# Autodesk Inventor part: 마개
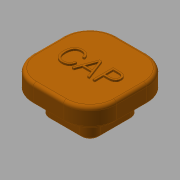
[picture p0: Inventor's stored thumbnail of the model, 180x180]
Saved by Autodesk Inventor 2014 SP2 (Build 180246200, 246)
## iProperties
Created: 2018-03
Part Number: 마개
Material: 고무
Document SubType Name: Modeling
Designer: mduedu
Density: 1 g/cm^3
Appearance: 주황색
Author: mduedu
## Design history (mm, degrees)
sketch "스케치1"
  geometry: L1 (12.5, 12.5)-(-12.5, 12.5); L2 (-12.5, 12.5)-(-12.5, -12.5); L3 (-12.5, -12.5)-(12.5, -12.5); L4 (12.5, -12.5)-(12.5, 12.5); L5 (12.5, 12.5)-(-12.5, -12.5); L6 (-12.5, 12.5)-(12.5, -12.5); 1 further point
  constraints: 12 end point, 2 midpoint, 2 parallel, 1 horizontal, 1 perpendicular
  dimensions: "d0" = 25 distance of L3.end L2.end; "d1" = 25 distance of L2.end L1.end
extrude "돌출1" new body sketch "스케치1" distance "d2" = 6; taper "d3" = 0 deg
fillet "모깎기1" dims "d4" = 8
fillet "모깎기2" dims "d5" = 1
sketch "스케치2"
  geometry: L1 (4.5, -12.5)-(-4.5, -12.5) reference; L2 (12.5, 4.5)-(12.5, -4.5) reference; L3 (-4.5, 12.5)-(4.5, 12.5) reference; L4 (-12.5, -4.5)-(-12.5, 4.5) reference; L5 (7.5, 4.5)-(7.5, -4.5); L6 (4.5, -7.5)-(-4.5, -7.5); L7 (-7.5, -4.5)-(-7.5, 4.5); L8 (-4.5, 7.5)-(4.5, 7.5); A1 r 8 centre (-4.5, -4.5) between (-12.5, -4.5) and (-4.5, -12.5) reference; A2 r 8 centre (4.5, -4.5) between (4.5, -12.5) and (12.5, -4.5) reference; A3 r 8 centre (4.5, 4.5) between (12.5, 4.5) and (4.5, 12.5) reference; A4 r 8 centre (-4.5, 4.5) between (-4.5, 12.5) and (-12.5, 4.5) reference; A5 r 3 centre (4.5, 4.5) between (7.5, 4.5) and (4.5, 7.5); A6 r 3 centre (4.5, -4.5) between (4.5, -7.5) and (7.5, -4.5); A7 r 3 centre (-4.5, -4.5) between (-7.5, -4.5) and (-4.5, -7.5); A8 r 3 centre (-4.5, 4.5) between (-4.5, 7.5) and (-7.5, 4.5); 1 further point
  constraints: 8 end point, 8 point on circle, 4 centre point, 7 other
  dimensions: "d6" = 5 distance between parallel lines of L8 L3
extrude "돌출2" join sketch "스케치2" distance "d7" = 6; taper "d8" = 0 deg
sketch "스케치3"
  geometry: L1 (4.5, 7.5)-(-4.5, 7.5) reference; L2 (-7.5, 4.5)-(-7.5, -4.5) reference; L3 (-4.5, -7.5)-(4.5, -7.5) reference; L4 (7.5, -4.5)-(7.5, 4.5) reference; L5 (-4.5, 5)-(4.5, 5); L6 (5, 4.5)-(5, -4.5); L7 (4.5, -5)-(-4.5, -5); L8 (-5, -4.5)-(-5, 4.5); A1 r 3 centre (4.5, 4.5) between (7.5, 4.5) and (4.5, 7.5) reference; A2 r 3 centre (-4.5, 4.5) between (-4.5, 7.5) and (-7.5, 4.5) reference; A3 r 3 centre (-4.5, -4.5) between (-7.5, -4.5) and (-4.5, -7.5) reference; A4 r 3 centre (4.5, -4.5) between (4.5, -7.5) and (7.5, -4.5) reference; A5 r 0.5 centre (4.5, 4.5) between (5, 4.5) and (4.5, 5); A6 r 0.5 centre (4.5, -4.5) between (4.5, -5) and (5, -4.5); A7 r 0.5 centre (-4.5, -4.5) between (-5, -4.5) and (-4.5, -5); A8 r 0.5 centre (-4.5, 4.5) between (-4.5, 5) and (-5, 4.5); 1 further point
  constraints: 8 end point, 8 point on circle, 4 centre point, 7 other
  dimensions: "d9" = 2.5 distance between parallel lines of L5 L1
extrude "돌출3" cut sketch "스케치3" stored distance "d10" = 10; taper "d11" = 0 deg
fillet "모깎기3" dims "d12" = 1
sketch "스케치4"
  geometry: L1 (7.5, 4.5)-(7.5, -4.5) reference; L2 (4.5, -7.5)-(-4.5, -7.5) reference; L3 (-7.5, -4.5)-(-7.5, 4.5) reference; L4 (-4.5, 7.5)-(4.5, 7.5) reference; L5 (4.5, -12.5)-(-4.5, -12.5) reference; L6 (12.5, 4.5)-(12.5, -4.5) reference; L7 (-4.5, 12.5)-(4.5, 12.5) reference; L8 (-12.5, -4.5)-(-12.5, 4.5) reference; L9 (11.5, 4.5)-(11.5, -4.5); L10 (4.5, -11.5)-(-4.5, -11.5); L11 (-11.5, -4.5)-(-11.5, 4.5); L12 (-4.5, 11.5)-(4.5, 11.5); A1 r 3 centre (4.5, -4.5) between (4.5, -7.5) and (7.5, -4.5) reference; A2 r 3 centre (-4.5, -4.5) between (-7.5, -4.5) and (-4.5, -7.5) reference; A3 r 3 centre (-4.5, 4.5) between (-4.5, 7.5) and (-7.5, 4.5) reference; A4 r 3 centre (4.5, 4.5) between (7.5, 4.5) and (4.5, 7.5) reference; A5 r 8 centre (-4.5, -4.5) between (-12.5, -4.5) and (-4.5, -12.5) reference; A6 r 8 centre (4.5, -4.5) between (4.5, -12.5) and (12.5, -4.5) reference; A7 r 8 centre (4.5, 4.5) between (12.5, 4.5) and (4.5, 12.5) reference; A8 r 8 centre (-4.5, 4.5) between (-4.5, 12.5) and (-12.5, 4.5) reference; A9 r 7 centre (4.5, 4.5) between (11.5, 4.5) and (4.5, 11.5); A10 r 7 centre (4.5, -4.5) between (4.5, -11.5) and (11.5, -4.5); A11 r 7 centre (-4.5, -4.5) between (-11.5, -4.5) and (-4.5, -11.5); A12 r 7 centre (-4.5, 4.5) between (-4.5, 11.5) and (-11.5, 4.5); 1 further point
  constraints: 8 end point, 8 point on circle, 4 centre point, 7 other
  dimensions: "d13" = 1 distance between parallel lines of L12 L7
extrude "돌출4" cut sketch "스케치4" distance "d14" = 1; taper "d15" = 0 deg
chamfer "모따기1" distance "d16" = 0.5; stored, may be unused: second distance "d17" = 2, angle "d18" = 45 deg
sketch "스케치5"
  geometry: 2 further points
  constraints: 1 coincident, 1 other
feature "엠보싱1" sketch "스케치5" dims "d0" = 25, "d1" = 25, "d19" = 0.5, "d20" = 0
node "솔리드1"
node "투영된 루프1"
node "투영된 루프2"
node "투영된 루프3"
